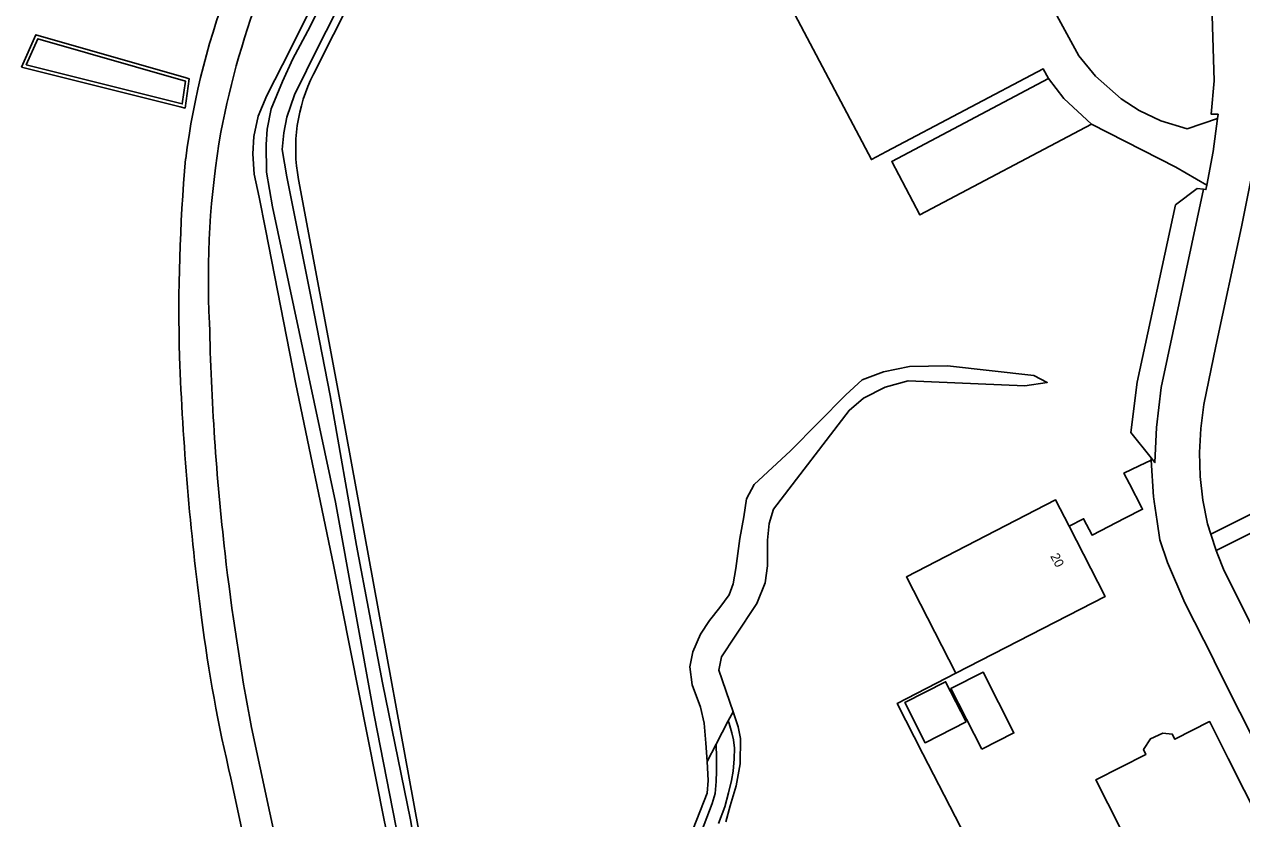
# Model space of a CAD drawing. Extents: x 158132 to 159664, y 385256 to 387218.
# Drawn here: x 158709.7 to 158842, y 386355 to 386441.3 of the extents above; entities that cross this region are included whole.
import ezdxf

# ---------------------------------------------------------------- set-up
doc = ezdxf.new("R2010")
doc.units = 0
for name, color, linetype in [('IMGEO_Erf', 7, 'Continuous'), ('IMGEO_Gemengd_bos', 7, 'Continuous'), ('IMGEO_Groenvoorziening', 7, 'Continuous'), ('IMGEO_Oever', 7, 'Continuous'), ('IMGEO_Pand', 7, 'Continuous'), ('IMGEO_Pand_nummerreeks', 7, 'Continuous'), ('IMGEO_Parkeervlak_open', 7, 'Continuous'), ('IMGEO_Rijbaan_lokaal_gesloten', 7, 'Continuous'), ('IMGEO_Rijbaan_lokaal_open', 7, 'Continuous'), ('IMGEO_Voetpad_open', 7, 'Continuous'), ('IMGEO_Waterloop', 7, 'Continuous')]:
    doc.layers.add(name, color=color, linetype=linetype)

msp = doc.modelspace()

# ---------------------------------------------------------------- linework, layer by layer
at = {"layer": 'IMGEO_Erf'}
for points in [[(158843.61, 386363.03), (158841.85, 386366.55), (158839.9, 386370.44), (158839.06, 386372.12), (158838.97, 386372.29), (158835.85, 386378.43), (158833.99, 386382.82), (158833.15, 386385.29), (158832.85, 386387.27), (158832.54, 386389.42), (158832.49, 386389.74), (158832.47, 386389.96), (158832.21, 386393.92), (158830.9, 386393.3), (158829.25, 386392.53), (158829.85, 386391.36), (158831.2, 386388.75), (158831.27, 386388.6), (158829.35, 386387.61), (158825.79, 386385.78), (158824.87, 386387.57), (158823.29, 386386.76), (158827.22, 386379.13), (158810.99, 386370.77), (158804.59, 386367.48), (158807.4, 386362.02), (158812.65, 386351.84)], [(158847.47, 386331.21), (158827.59, 386321.1), (158825.78, 386324.64), (158824.45, 386324.71), (158823.78, 386326.03), (158824.31, 386327.66), (158822.36, 386331.49), (158838.82, 386339.86), (158834.91, 386347.54), (158832.68, 386346.41), (158826.18, 386359.19), (158831.64, 386361.96), (158831.38, 386362.48), (158832.15, 386363.66), (158833.46, 386364.27), (158834.5, 386364.17), (158834.78, 386363.61), (158838.56, 386365.53), (158838.65, 386365.34), (158840.59, 386361.52), (158847.51, 386347.83)]]:
    msp.add_lwpolyline(points, dxfattribs=at)
for points in [[(158813.8, 386362.53), (158810.44, 386369.13), (158813.93, 386370.9), (158817.28, 386364.3)], [(158812.08, 386365.49), (158807.64, 386363.23), (158805.42, 386367.59), (158809.86, 386369.85)]]:
    msp.add_lwpolyline(points, close=True, dxfattribs=at)
at = {"layer": 'IMGEO_Gemengd_bos'}
for points in [[(158815.03, 386532.59), (158815.82, 386530.22), (158818.94, 386521.12), (158819.46, 386520.12), (158822.01, 386507.82), (158822.56, 386500.36), (158821.42, 386496.79), (158820.16, 386495.14), (158819.22, 386493.84), (158815.04, 386489.85), (158811.53, 386487.03), (158804.62, 386483.01), (158788.92, 386474.18), (158762.38, 386460.33), (158751.88, 386454.91), (158749.9, 386453.2), (158741.14, 386435.86)], [(158755.63, 386323.95), (158754.93, 386327.04), (158748.86, 386354.64), (158743.31, 386382.56), (158739.24, 386402.17), (158735.92, 386419.01), (158735.24, 386422.5), (158734.72, 386424.99), (158734.55, 386427.23), (158734.67, 386429.11), (158735.15, 386431.32), (158736.09, 386433.56), (158738.64, 386438.6), (158746.9, 386455.19)], [(158821.82, 386389.61), (158823.29, 386386.76), (158824.87, 386387.57), (158825.79, 386385.78), (158829.35, 386387.61), (158831.27, 386388.6), (158831.2, 386388.75), (158829.85, 386391.36), (158829.25, 386392.53), (158830.9, 386393.3), (158832.21, 386393.92), (158832.19, 386394.2), (158830.01, 386396.92), (158830.69, 386402.4), (158834.87, 386421.66), (158837.21, 386423.46), (158837.9, 386423.36), (158838.16, 386423.33), (158838.25, 386423.8), (158834.9, 386425.77), (158825.73, 386430.42), (158807.07, 386420.58), (158804, 386426.39), (158821.03, 386435.38), (158820.46, 386436.45), (158803.43, 386427.46), (158801.79, 386426.59), (158793.47, 386442.36)], [(158739.51, 386424.44), (158744.28, 386399.14), (158755.47, 386338)], [(158782.41, 386353.87), (158783.93, 386357.73), (158784.05, 386359.12), (158783.93, 386361.18), (158783.8, 386363.18), (158783.63, 386365.34), (158783.21, 386367.08), (158782.33, 386369.52), (158782.05, 386371.49), (158782.37, 386373.12), (158783.21, 386375.01), (158784.19, 386376.5), (158785.31, 386377.92), (158786.33, 386379.3), (158786.77, 386380.49), (158787.07, 386382.16), (158787.49, 386385.42), (158787.92, 386387.79), (158788.23, 386389.73), (158789.04, 386391.27), (158793, 386394.95), (158799.01, 386401.01), (158800.81, 386402.64), (158803.12, 386403.54), (158805.92, 386404.09), (158810.08, 386404.18), (158819.47, 386403.14), (158820.92, 386402.37), (158818.48, 386402.01), (158805.78, 386402.55), (158803.3, 386401.87), (158800.95, 386400.65), (158799.37, 386399.34), (158791.15, 386388.59), (158790.7, 386387.05), (158790.51, 386385.25), (158790.51, 386382.45), (158790.24, 386380.6), (158789.34, 386378.34), (158786.99, 386374.81), (158785.5, 386372.55), (158785.23, 386371.11), (158786.76, 386366.6), (158787.33, 386364.94), (158787.57, 386363.68), (158787.53, 386360.93), (158787.1, 386358.55), (158786.45, 386356.36), (158785.97, 386354.65)], [(158825.57, 386309.56), (158819.55, 386320.12), (158817.96, 386321.33), (158813.41, 386330.36), (158820.91, 386334.22), (158812.65, 386351.84), (158807.4, 386362.02), (158804.59, 386367.48), (158810.99, 386370.77), (158805.6, 386381.25), (158821.82, 386389.61)], [(158734.4, 386364.89), (158743.33, 386323.41), (158746.02, 386311.65), (158749.3, 386298.68), (158751.42, 386291.23), (158753.61, 386283.48), (158757.33, 386271.45), (158764.42, 386250), (158774.64, 386219.06)], [(158730.77, 386256.7), (158738.34, 386270.94), (158739.86, 386274.2), (158742.7, 386279.18), (158745.33, 386283.37), (158748.7, 386288.27), (158742.74, 386310.8), (158740.13, 386322.23), (158732.17, 386359.37)]]:
    msp.add_lwpolyline(points, dxfattribs=at)
msp.add_lwpolyline([(158709.42, 386436.64), (158710.98, 386440.16), (158727.32, 386435.46), (158727.63, 386435.37), (158727.19, 386432.18), (158726.64, 386432.32)], close=True, dxfattribs=at)
for centre, radius, start, end in [((158806.54, 386416.79), 79.89, 158.1763, 172.9044), ((158821.96, 386412.32), 92.49, 158.7717, 169.2508), ((158757.2, 386427.75), 17.99, 153.1854, 190.5979), ((158822.47, 386413.68), 92.75, 170.1343, 183.0174), ((158914.06, 386410.09), 187.54, 174.9315, 181.5121), ((158993.77, 386414.07), 263.97, 181.1448, 186.5873), ((159028.95, 386416.44), 302.57, 182.1399, 187.5181), ((158997.01, 386414.38), 267.23, 186.5729, 190.6724), ((158891.98, 386397.6), 164.31, 187.2563, 193.4566)]:
    msp.add_arc(centre, radius, start, end, dxfattribs=at)
at = {"layer": 'IMGEO_Groenvoorziening'}
msp.add_lwpolyline([(158833.34, 386486.39), (158833.28, 386486.8), (158824.09, 386481.84), (158814.87, 386477.09), (158815.08, 386476.68), (158827.22, 386452.91), (158819.8, 386448.9), (158820.85, 386446.91), (158819.81, 386446.38), (158821.72, 386442.65), (158824.34, 386437.85), (158826.15, 386435.66), (158828.94, 386433.18), (158830.92, 386431.92), (158833.25, 386430.8), (158836.12, 386429.94), (158839.41, 386431.05), (158839.48, 386431.51), (158838.72, 386431.53), (158839.04, 386435.13), (158838.6, 386450.54), (158837.65, 386456.47), (158836.52, 386464.72)], close=True, dxfattribs=at)
for points in [[(158843.56, 386426.89), (158842.03, 386419.28), (158839.23, 386406.31), (158837.93, 386399.96), (158837.59, 386397.37), (158837.46, 386394.77), (158837.54, 386392.16), (158837.84, 386389.57), (158838.34, 386387.01), (158838.71, 386385.88), (158854.35, 386393.71)], [(158854.42, 386391.72), (158839.29, 386384.11), (158839.44, 386383.64), (158840.07, 386382.07), (158841.16, 386379.89), (158846.33, 386369.6)]]:
    msp.add_lwpolyline(points, dxfattribs=at)
at = {"layer": 'IMGEO_Oever'}
for points in [[(158741.14, 386435.86), (158749.9, 386453.2), (158751.88, 386454.91), (158762.38, 386460.33), (158788.92, 386474.18), (158804.62, 386483.01), (158811.53, 386487.03), (158815.04, 386489.85), (158819.22, 386493.84), (158820.16, 386495.14), (158821.42, 386496.79), (158822.56, 386500.36), (158822.01, 386507.82), (158819.46, 386520.12), (158818.94, 386521.12), (158815.82, 386530.22), (158815.03, 386532.59)], [(158746.9, 386455.19), (158738.64, 386438.6), (158736.09, 386433.56), (158735.15, 386431.32), (158734.67, 386429.11), (158734.55, 386427.23), (158734.72, 386424.99), (158735.24, 386422.5), (158735.92, 386419.01), (158739.24, 386402.17), (158743.31, 386382.56), (158748.86, 386354.64), (158754.93, 386327.04), (158755.63, 386323.95)], [(158749.3, 386453.83), (158741.69, 386438.9), (158739.08, 386433.62), (158738.24, 386431.21), (158737.93, 386429.5), (158737.75, 386427.7), (158738.25, 386424.73), (158740.93, 386411.36), (158742.95, 386400.97), (158745.84, 386384.66), (158748.64, 386369.72), (158751.69, 386354.85), (158754.48, 386338.82), (158756.11, 386332.57), (158757.24, 386327.82), (158758.56, 386326.01), (158758.57, 386325.99)], [(158753.51, 386336.81), (158747.76, 386366.21), (158743.56, 386389.35), (158736.69, 386421.47), (158736.05, 386425.22), (158736.02, 386428.24), (158736.13, 386429.9), (158736.54, 386432.1), (158737.79, 386435.07), (158738.91, 386437.52), (158740.8, 386441.03), (158745.74, 386451.17)], [(158758.57, 386325.99), (158757.66, 386330.04), (158755.47, 386338), (158744.28, 386399.14), (158739.51, 386424.44)], [(158785.97, 386354.65), (158786.45, 386356.36), (158787.1, 386358.55), (158787.53, 386360.93), (158787.57, 386363.68), (158787.33, 386364.94), (158786.76, 386366.6), (158786.24, 386365.61), (158786.35, 386365.32), (158786.64, 386364.31), (158786.81, 386363.54), (158786.91, 386362.62), (158786.89, 386361.48), (158786.78, 386360.13), (158786.59, 386359.14), (158786.27, 386357.77), (158785.85, 386356.27), (158785.17, 386354.46)], [(158783.34, 386353.57), (158783.9, 386355.1), (158784.48, 386356.61), (158784.83, 386357.71), (158784.93, 386359.02), (158784.95, 386360.14), (158784.95, 386361.71), (158784.93, 386362.98), (158784.92, 386363.08), (158783.93, 386361.18), (158784.05, 386359.12), (158783.93, 386357.73), (158782.41, 386353.87)]]:
    msp.add_lwpolyline(points, dxfattribs=at)
for points in [[(158709.42, 386436.64), (158726.64, 386432.32), (158727.19, 386432.18), (158727.63, 386435.37), (158727.32, 386435.46), (158710.98, 386440.16)], [(158709.93, 386436.89), (158711.18, 386439.72), (158727.22, 386435.11), (158726.88, 386432.64)]]:
    msp.add_lwpolyline(points, close=True, dxfattribs=at)
msp.add_arc((158757.2, 386427.75), 17.99, 153.1854, 190.5979, dxfattribs=at)
at = {"layer": 'IMGEO_Pand'}
for points in [[(158823.29, 386386.76), (158821.82, 386389.61), (158805.6, 386381.25), (158810.99, 386370.77), (158827.22, 386379.13)], [(158813.8, 386362.53), (158817.28, 386364.3), (158813.93, 386370.9), (158810.44, 386369.13)], [(158812.08, 386365.49), (158809.86, 386369.85), (158805.42, 386367.59), (158807.64, 386363.23)]]:
    msp.add_lwpolyline(points, close=True, dxfattribs=at)
msp.add_lwpolyline([(158847.51, 386347.83), (158840.59, 386361.52), (158838.65, 386365.34), (158838.56, 386365.53), (158834.78, 386363.61), (158834.5, 386364.17), (158833.46, 386364.27), (158832.15, 386363.66), (158831.38, 386362.48), (158831.64, 386361.96), (158826.18, 386359.19), (158832.68, 386346.41), (158834.91, 386347.54), (158838.82, 386339.86), (158822.36, 386331.49), (158824.31, 386327.66), (158823.78, 386326.03), (158824.45, 386324.71), (158825.78, 386324.64), (158827.59, 386321.1), (158847.47, 386331.21)], dxfattribs=at)
at = {"layer": 'IMGEO_Parkeervlak_open'}
msp.add_lwpolyline([(158837.9, 386423.36), (158837.21, 386423.46), (158834.87, 386421.66), (158830.69, 386402.4), (158830.01, 386396.92), (158832.19, 386394.2), (158832.62, 386393.66), (158832.77, 386397.48), (158833.29, 386401.81)], close=True, dxfattribs=at)
at = {"layer": 'IMGEO_Rijbaan_lokaal_gesloten'}
for points in [[(158838.6, 386450.54), (158839.04, 386435.13), (158838.72, 386431.53), (158839.48, 386431.51), (158839.41, 386431.05), (158838.94, 386427.47), (158838.25, 386423.8), (158838.16, 386423.33), (158837.9, 386423.36), (158833.29, 386401.81), (158832.77, 386397.48), (158832.62, 386393.66), (158832.19, 386394.2), (158832.21, 386393.92), (158832.47, 386389.96), (158832.49, 386389.74), (158832.54, 386389.42), (158832.85, 386387.27), (158833.15, 386385.29), (158833.99, 386382.82), (158835.85, 386378.43), (158838.97, 386372.29), (158839.06, 386372.12), (158839.9, 386370.44), (158841.85, 386366.55), (158843.61, 386363.03)], [(158846.33, 386369.6), (158841.16, 386379.89), (158840.07, 386382.07), (158839.44, 386383.64), (158839.29, 386384.11), (158838.71, 386385.88), (158838.34, 386387.01), (158837.84, 386389.57), (158837.54, 386392.16), (158837.46, 386394.77), (158837.59, 386397.37), (158837.93, 386399.96), (158839.23, 386406.31), (158842.03, 386419.28), (158843.56, 386426.89)], [(158764.42, 386250), (158757.33, 386271.45), (158753.61, 386283.48), (158751.42, 386291.23), (158749.3, 386298.68), (158746.02, 386311.65), (158743.33, 386323.41), (158734.4, 386364.89)], [(158732.17, 386359.37), (158740.13, 386322.23), (158742.74, 386310.8), (158748.7, 386288.27), (158749.06, 386286.9), (158749.33, 386285.89), (158749.77, 386284.41), (158751.56, 386278.38), (158760.94, 386250), (158771.5, 386218.02), (158774.64, 386219.06), (158764.42, 386250)]]:
    msp.add_lwpolyline(points, dxfattribs=at)
for centre, radius, start, end in [((158806.54, 386416.79), 79.89, 158.1763, 172.9044), ((158821.96, 386412.32), 92.49, 158.7717, 169.2508), ((158822.47, 386413.68), 92.75, 170.1343, 183.0174), ((158914.06, 386410.09), 187.54, 174.9315, 181.5121), ((158993.77, 386414.07), 263.97, 181.1448, 186.5873), ((159028.95, 386416.44), 302.57, 182.1399, 187.5181), ((158997.01, 386414.38), 267.23, 186.5729, 190.6724), ((158891.98, 386397.6), 164.31, 187.2563, 193.4566)]:
    msp.add_arc(centre, radius, start, end, dxfattribs=at)
at = {"layer": 'IMGEO_Rijbaan_lokaal_open'}
msp.add_lwpolyline([(158819.8, 386448.9), (158817.46, 386453.34), (158816.76, 386454.66), (158793.47, 386442.36), (158801.79, 386426.59), (158803.43, 386427.46), (158820.46, 386436.45), (158821.03, 386435.38), (158822.71, 386433.23), (158825.73, 386430.42), (158834.9, 386425.77), (158838.25, 386423.8), (158838.94, 386427.47), (158839.41, 386431.05), (158836.12, 386429.94), (158833.25, 386430.8), (158830.92, 386431.92), (158828.94, 386433.18), (158826.15, 386435.66), (158824.34, 386437.85), (158821.72, 386442.65), (158819.81, 386446.38), (158820.85, 386446.91)], close=True, dxfattribs=at)
at = {"layer": 'IMGEO_Voetpad_open'}
for points in [[(158838.71, 386385.88), (158839.29, 386384.11), (158854.42, 386391.72), (158860.64, 386389.79), (158876.53, 386397.99), (158881.22, 386396.45), (158951.64, 386432.17), (158954.64, 386431.27), (158969.75, 386438.88), (158968.14, 386440.2), (158954.45, 386433.39), (158951.46, 386434.27), (158880.9, 386398.53), (158876.51, 386400.14), (158860.27, 386391.85), (158854.35, 386393.71)], [(158825.73, 386430.42), (158822.71, 386433.23), (158821.03, 386435.38), (158804, 386426.39), (158807.07, 386420.58)]]:
    msp.add_lwpolyline(points, close=True, dxfattribs=at)
at = {"layer": 'IMGEO_Waterloop'}
for points in [[(158751.69, 386354.85), (158748.64, 386369.72), (158745.84, 386384.66), (158742.95, 386400.97), (158740.93, 386411.36), (158738.25, 386424.73), (158737.75, 386427.7), (158737.93, 386429.5), (158738.24, 386431.21), (158739.08, 386433.62), (158741.69, 386438.9), (158749.3, 386453.83)], [(158745.74, 386451.17), (158740.8, 386441.03), (158738.91, 386437.52), (158737.79, 386435.07), (158736.54, 386432.1), (158736.13, 386429.9), (158736.02, 386428.24), (158736.05, 386425.22), (158736.69, 386421.47), (158743.56, 386389.35), (158747.76, 386366.21), (158753.51, 386336.81)], [(158785.17, 386354.46), (158785.85, 386356.27), (158786.27, 386357.77), (158786.59, 386359.14), (158786.78, 386360.13), (158786.89, 386361.48), (158786.91, 386362.62), (158786.81, 386363.54), (158786.64, 386364.31), (158786.35, 386365.32), (158786.24, 386365.61), (158784.92, 386363.08), (158784.93, 386362.98), (158784.95, 386361.71), (158784.95, 386360.14), (158784.93, 386359.02), (158784.83, 386357.71), (158784.48, 386356.61), (158783.9, 386355.1), (158783.34, 386353.57)]]:
    msp.add_lwpolyline(points, dxfattribs=at)
for points in [[(158727.22, 386435.11), (158711.18, 386439.72), (158709.93, 386436.89), (158726.88, 386432.64)], [(158789.34, 386378.34), (158790.24, 386380.6), (158790.51, 386382.45), (158790.51, 386385.25), (158790.7, 386387.05), (158791.15, 386388.59), (158799.37, 386399.34), (158800.95, 386400.65), (158803.3, 386401.87), (158805.78, 386402.55), (158818.48, 386402.01), (158820.92, 386402.37), (158819.47, 386403.14), (158810.08, 386404.18), (158805.92, 386404.09), (158803.12, 386403.54), (158800.81, 386402.64), (158799.01, 386401.01), (158793, 386394.95), (158789.04, 386391.27), (158788.23, 386389.73), (158787.92, 386387.79), (158787.49, 386385.42), (158787.07, 386382.16), (158786.77, 386380.49), (158786.33, 386379.3), (158785.31, 386377.92), (158784.19, 386376.5), (158783.21, 386375.01), (158782.37, 386373.12), (158782.05, 386371.49), (158782.33, 386369.52), (158783.21, 386367.08), (158783.63, 386365.34), (158783.8, 386363.18), (158783.93, 386361.18), (158784.92, 386363.08), (158786.24, 386365.61), (158786.76, 386366.6), (158785.23, 386371.11), (158785.5, 386372.55), (158786.99, 386374.81)]]:
    msp.add_lwpolyline(points, close=True, dxfattribs=at)

# ---------------------------------------------------------------- texts
at = {"layer": 'IMGEO_Pand_nummerreeks'}
msp.add_text('20', height=1, rotation=297.6221, dxfattribs=at).set_placement((158821.22, 386383.5))

doc.saveas('drawing.dxf')
